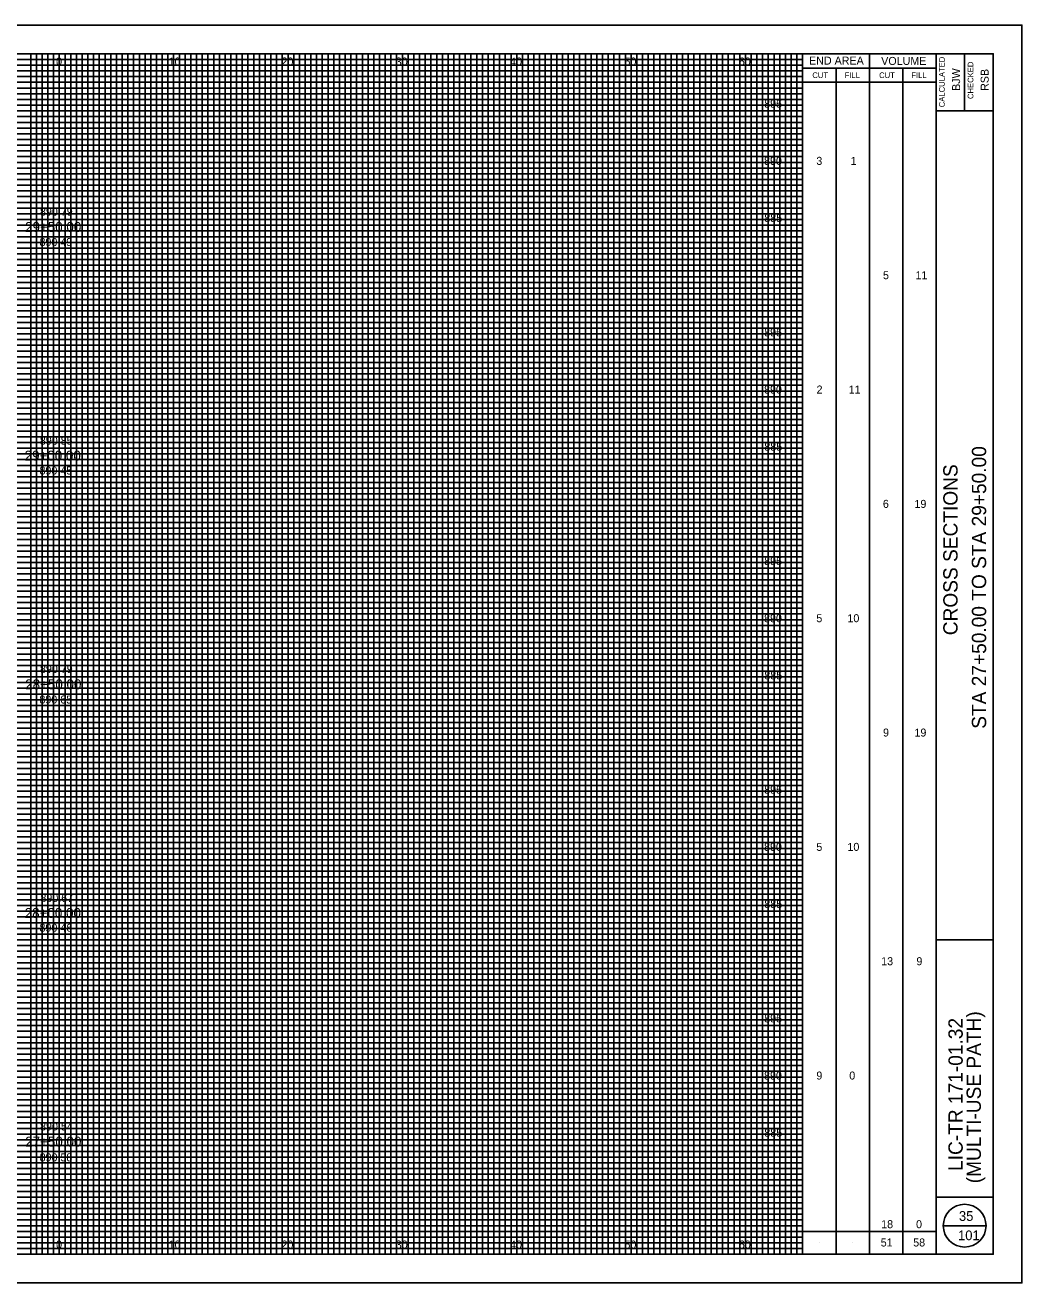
# Model space of a CAD drawing. Extents: x -10 to 160, y -2 to 2522.
# Drawn here: x 72.8 to 160, y 802.5 to 912.5 of the extents above; entities that cross this region are included whole.
import ezdxf

# ---------------------------------------------------------------- set-up
doc = ezdxf.new("R2010")
doc.units = 0
for name, color, linetype in [('GK_Cells', 7, 'Continuous'), ('GK_Patterns', 7, 'Continuous'), ('TX_P_10', 7, 'Continuous'), ('TX_X_10', 7, 'Continuous'), ('XS_P_Finished_Grade_Seeded', 7, 'Continuous'), ('XS_P_Pavt_Surface', 7, 'Continuous'), ('XS_P_Subgrade', 7, 'Continuous'), ('XS_X_Ground_Line', 7, 'Continuous')]:
    doc.layers.add(name, color=color, linetype=linetype)

msp = doc.modelspace()

# ---------------------------------------------------------------- linework, layer by layer
at = {"layer": 'GK_Cells'}
msp.add_lwpolyline([(-10, 802.5), (160, 802.5), (160, 912.5), (-10, 912.5)], close=True, dxfattribs=at)
at = {"layer": 'TX_P_10'}
for p, q in [((140.83, 805), (140.83, 910)), ((146.67, 805), (146.67, 910)), ((140.83, 908.75), (152.5, 908.75)), ((143.75, 805), (143.75, 908.75)), ((149.58, 805), (149.58, 908.75)), ((140.83, 907.5), (152.5, 907.5)), ((153.12, 807.5), (156.88, 807.5)), ((140.83, 807), (152.5, 807)), ((142.29, 806), (142.29, 806)), ((145.21, 806), (145.21, 806)), ((148.12, 806), (148.12, 806)), ((151.04, 806), (151.04, 806))]:
    msp.add_line(p, q, dxfattribs=at)
msp.add_circle((155, 807.5), 1.87, dxfattribs=at)
at = {"layer": 'TX_X_10'}
for p, q in [((75.83, 805), (75.83, 910)), ((80.83, 805), (80.83, 910)), ((85.83, 805), (85.83, 910)), ((90.83, 805), (90.83, 910)), ((95.83, 805), (95.83, 910)), ((100.83, 805), (100.83, 910)), ((105.83, 805), (105.83, 910)), ((110.83, 805), (110.83, 910)), ((115.83, 805), (115.83, 910)), ((120.83, 805), (120.83, 910)), ((125.83, 805), (125.83, 910)), ((130.83, 805), (130.83, 910)), ((135.83, 805), (135.83, 910)), ((5.83, 905), (140.83, 905)), ((5.83, 900), (140.83, 900)), ((5.83, 895), (140.83, 895)), ((5.83, 890), (140.83, 890)), ((5.83, 885), (140.83, 885)), ((5.83, 880), (140.83, 880)), ((5.83, 875), (140.83, 875)), ((5.83, 870), (140.83, 870)), ((5.83, 865), (140.83, 865)), ((5.83, 860), (140.83, 860)), ((5.83, 855), (140.83, 855)), ((5.83, 850), (140.83, 850)), ((5.83, 845), (140.83, 845)), ((5.83, 840), (140.83, 840)), ((5.83, 835), (140.83, 835)), ((5.83, 830), (140.83, 830)), ((5.83, 825), (140.83, 825)), ((5.83, 820), (140.83, 820)), ((5.83, 815), (140.83, 815)), ((5.83, 810), (140.83, 810))]:
    msp.add_line(p, q, dxfattribs=at)
at = {"layer": 'XS_P_Pavt_Surface'}
for p, q in [((152.5, 805), (152.5, 910)), ((155, 910), (155, 905)), ((152.5, 905), (157.5, 905)), ((152.5, 832.5), (157.5, 832.5)), ((152.5, 810), (157.5, 810))]:
    msp.add_line(p, q, dxfattribs=at)
msp.add_lwpolyline([(0, 910), (157.5, 910), (157.5, 805), (0, 805)], close=True, dxfattribs=at)
at = {"layer": 'XS_X_Ground_Line'}
for p, q in [((73.33, 805), (73.33, 910)), ((73.83, 805), (73.83, 910)), ((74.33, 805), (74.33, 910)), ((74.83, 805), (74.83, 910)), ((75.33, 805), (75.33, 910)), ((76.33, 805), (76.33, 910)), ((76.83, 805), (76.83, 910)), ((77.33, 805), (77.33, 910)), ((77.83, 805), (77.83, 910)), ((78.33, 805), (78.33, 910)), ((78.83, 805), (78.83, 910)), ((79.33, 805), (79.33, 910)), ((79.83, 805), (79.83, 910)), ((80.33, 805), (80.33, 910)), ((81.33, 805), (81.33, 910)), ((81.83, 805), (81.83, 910)), ((82.33, 805), (82.33, 910)), ((82.83, 805), (82.83, 910)), ((83.33, 805), (83.33, 910)), ((83.83, 805), (83.83, 910)), ((84.33, 805), (84.33, 910)), ((84.83, 805), (84.83, 910)), ((85.33, 805), (85.33, 910)), ((86.33, 805), (86.33, 910)), ((86.83, 805), (86.83, 910)), ((87.33, 805), (87.33, 910)), ((87.83, 805), (87.83, 910)), ((88.33, 805), (88.33, 910)), ((88.83, 805), (88.83, 910)), ((89.33, 805), (89.33, 910)), ((89.83, 805), (89.83, 910)), ((90.33, 805), (90.33, 910)), ((91.33, 805), (91.33, 910)), ((91.83, 805), (91.83, 910)), ((92.33, 805), (92.33, 910)), ((92.83, 805), (92.83, 910)), ((93.33, 805), (93.33, 910)), ((93.83, 805), (93.83, 910)), ((94.33, 805), (94.33, 910)), ((94.83, 805), (94.83, 910)), ((95.33, 805), (95.33, 910)), ((96.33, 805), (96.33, 910)), ((96.83, 805), (96.83, 910)), ((97.33, 805), (97.33, 910)), ((97.83, 805), (97.83, 910)), ((98.33, 805), (98.33, 910)), ((98.83, 805), (98.83, 910)), ((99.33, 805), (99.33, 910)), ((99.83, 805), (99.83, 910)), ((100.33, 805), (100.33, 910)), ((101.33, 805), (101.33, 910)), ((101.83, 805), (101.83, 910)), ((102.33, 805), (102.33, 910)), ((102.83, 805), (102.83, 910)), ((103.33, 805), (103.33, 910)), ((103.83, 805), (103.83, 910)), ((104.33, 805), (104.33, 910)), ((104.83, 805), (104.83, 910)), ((105.33, 805), (105.33, 910)), ((106.33, 805), (106.33, 910)), ((106.83, 805), (106.83, 910)), ((107.33, 805), (107.33, 910)), ((107.83, 805), (107.83, 910)), ((108.33, 805), (108.33, 910)), ((108.83, 805), (108.83, 910)), ((109.33, 805), (109.33, 910)), ((109.83, 805), (109.83, 910)), ((110.33, 805), (110.33, 910)), ((111.33, 805), (111.33, 910)), ((111.83, 805), (111.83, 910)), ((112.33, 805), (112.33, 910)), ((112.83, 805), (112.83, 910)), ((113.33, 805), (113.33, 910)), ((113.83, 805), (113.83, 910)), ((114.33, 805), (114.33, 910)), ((114.83, 805), (114.83, 910)), ((115.33, 805), (115.33, 910)), ((116.33, 805), (116.33, 910)), ((116.83, 805), (116.83, 910)), ((117.33, 805), (117.33, 910)), ((117.83, 805), (117.83, 910)), ((118.33, 805), (118.33, 910)), ((118.83, 805), (118.83, 910)), ((119.33, 805), (119.33, 910)), ((119.83, 805), (119.83, 910)), ((120.33, 805), (120.33, 910)), ((121.33, 805), (121.33, 910)), ((121.83, 805), (121.83, 910)), ((122.33, 805), (122.33, 910)), ((122.83, 805), (122.83, 910)), ((123.33, 805), (123.33, 910)), ((123.83, 805), (123.83, 910)), ((124.33, 805), (124.33, 910)), ((124.83, 805), (124.83, 910)), ((125.33, 805), (125.33, 910)), ((126.33, 805), (126.33, 910)), ((126.83, 805), (126.83, 910)), ((127.33, 805), (127.33, 910)), ((127.83, 805), (127.83, 910)), ((128.33, 805), (128.33, 910)), ((128.83, 805), (128.83, 910)), ((129.33, 805), (129.33, 910)), ((129.83, 805), (129.83, 910)), ((130.33, 805), (130.33, 910)), ((131.33, 805), (131.33, 910)), ((131.83, 805), (131.83, 910)), ((132.33, 805), (132.33, 910)), ((132.83, 805), (132.83, 910)), ((133.33, 805), (133.33, 910)), ((133.83, 805), (133.83, 910)), ((134.33, 805), (134.33, 910)), ((134.83, 805), (134.83, 910)), ((135.33, 805), (135.33, 910)), ((136.33, 805), (136.33, 910)), ((136.83, 805), (136.83, 910)), ((137.33, 805), (137.33, 910)), ((137.83, 805), (137.83, 910)), ((138.33, 805), (138.33, 910)), ((138.83, 805), (138.83, 910)), ((139.33, 805), (139.33, 910)), ((139.83, 805), (139.83, 910)), ((140.33, 805), (140.33, 910)), ((5.83, 909.5), (140.83, 909.5)), ((5.83, 909), (140.83, 909)), ((5.83, 908.5), (140.83, 908.5)), ((5.83, 908), (140.83, 908)), ((5.83, 907.5), (140.83, 907.5)), ((5.83, 907), (140.83, 907)), ((5.83, 906.5), (140.83, 906.5)), ((5.83, 906), (140.83, 906)), ((5.83, 905.5), (140.83, 905.5)), ((5.83, 904.5), (140.83, 904.5)), ((5.83, 904), (140.83, 904)), ((5.83, 903.5), (140.83, 903.5)), ((5.83, 903), (140.83, 903)), ((5.83, 902.5), (140.83, 902.5)), ((5.83, 902), (140.83, 902)), ((5.83, 901.5), (140.83, 901.5)), ((5.83, 901), (140.83, 901)), ((5.83, 900.5), (140.83, 900.5)), ((5.83, 899.5), (140.83, 899.5)), ((5.83, 899), (140.83, 899)), ((5.83, 898.5), (140.83, 898.5)), ((5.83, 898), (140.83, 898)), ((5.83, 897.5), (140.83, 897.5)), ((5.83, 897), (140.83, 897)), ((5.83, 896.5), (140.83, 896.5)), ((5.83, 896), (140.83, 896)), ((5.83, 895.5), (140.83, 895.5)), ((5.83, 894.5), (140.83, 894.5)), ((5.83, 894), (140.83, 894)), ((5.83, 893.5), (140.83, 893.5)), ((5.83, 893), (140.83, 893)), ((5.83, 892.5), (140.83, 892.5)), ((5.83, 892), (140.83, 892)), ((5.83, 891.5), (140.83, 891.5)), ((5.83, 891), (140.83, 891)), ((5.83, 890.5), (140.83, 890.5)), ((5.83, 889.5), (140.83, 889.5)), ((5.83, 889), (140.83, 889)), ((5.83, 888.5), (140.83, 888.5)), ((5.83, 888), (140.83, 888)), ((5.83, 887.5), (140.83, 887.5)), ((5.83, 887), (140.83, 887)), ((5.83, 886.5), (140.83, 886.5)), ((5.83, 886), (140.83, 886)), ((5.83, 885.5), (140.83, 885.5)), ((5.83, 884.5), (140.83, 884.5)), ((5.83, 884), (140.83, 884)), ((5.83, 883.5), (140.83, 883.5)), ((5.83, 883), (140.83, 883)), ((5.83, 882.5), (140.83, 882.5)), ((5.83, 882), (140.83, 882)), ((5.83, 881.5), (140.83, 881.5)), ((5.83, 881), (140.83, 881)), ((5.83, 880.5), (140.83, 880.5)), ((5.83, 879.5), (140.83, 879.5)), ((5.83, 879), (140.83, 879)), ((5.83, 878.5), (140.83, 878.5)), ((5.83, 878), (140.83, 878)), ((5.83, 877.5), (140.83, 877.5)), ((5.83, 877), (140.83, 877)), ((5.83, 876.5), (140.83, 876.5)), ((5.83, 876), (140.83, 876)), ((5.83, 875.5), (140.83, 875.5)), ((5.83, 874.5), (140.83, 874.5)), ((5.83, 874), (140.83, 874)), ((5.83, 873.5), (140.83, 873.5)), ((5.83, 873), (140.83, 873)), ((5.83, 872.5), (140.83, 872.5)), ((5.83, 872), (140.83, 872)), ((5.83, 871.5), (140.83, 871.5)), ((5.83, 871), (140.83, 871)), ((5.83, 870.5), (140.83, 870.5)), ((5.83, 869.5), (140.83, 869.5)), ((5.83, 869), (140.83, 869)), ((5.83, 868.5), (140.83, 868.5)), ((5.83, 868), (140.83, 868)), ((5.83, 867.5), (140.83, 867.5)), ((5.83, 867), (140.83, 867)), ((5.83, 866.5), (140.83, 866.5)), ((5.83, 866), (140.83, 866)), ((5.83, 865.5), (140.83, 865.5)), ((5.83, 864.5), (140.83, 864.5)), ((5.83, 864), (140.83, 864)), ((5.83, 863.5), (140.83, 863.5)), ((5.83, 863), (140.83, 863)), ((5.83, 862.5), (140.83, 862.5)), ((5.83, 862), (140.83, 862)), ((5.83, 861.5), (140.83, 861.5)), ((5.83, 861), (140.83, 861)), ((5.83, 860.5), (140.83, 860.5)), ((5.83, 859.5), (140.83, 859.5)), ((5.83, 859), (140.83, 859)), ((5.83, 858.5), (140.83, 858.5)), ((5.83, 858), (140.83, 858)), ((5.83, 857.5), (140.83, 857.5)), ((5.83, 857), (140.83, 857)), ((5.83, 856.5), (140.83, 856.5)), ((5.83, 856), (140.83, 856)), ((5.83, 855.5), (140.83, 855.5)), ((5.83, 854.5), (140.83, 854.5)), ((5.83, 854), (140.83, 854)), ((5.83, 853.5), (140.83, 853.5)), ((5.83, 853), (140.83, 853)), ((5.83, 852.5), (140.83, 852.5)), ((5.83, 852), (140.83, 852)), ((5.83, 851.5), (140.83, 851.5)), ((5.83, 851), (140.83, 851)), ((5.83, 850.5), (140.83, 850.5)), ((5.83, 849.5), (140.83, 849.5)), ((5.83, 849), (140.83, 849)), ((5.83, 848.5), (140.83, 848.5)), ((5.83, 848), (140.83, 848)), ((5.83, 847.5), (140.83, 847.5)), ((5.83, 847), (140.83, 847)), ((5.83, 846.5), (140.83, 846.5)), ((5.83, 846), (140.83, 846)), ((5.83, 845.5), (140.83, 845.5)), ((5.83, 844.5), (140.83, 844.5)), ((5.83, 844), (140.83, 844)), ((5.83, 843.5), (140.83, 843.5)), ((5.83, 843), (140.83, 843)), ((5.83, 842.5), (140.83, 842.5)), ((5.83, 842), (140.83, 842)), ((5.83, 841.5), (140.83, 841.5)), ((5.83, 841), (140.83, 841)), ((5.83, 840.5), (140.83, 840.5)), ((5.83, 839.5), (140.83, 839.5)), ((5.83, 839), (140.83, 839)), ((5.83, 838.5), (140.83, 838.5)), ((5.83, 838), (140.83, 838)), ((5.83, 837.5), (140.83, 837.5)), ((5.83, 837), (140.83, 837)), ((5.83, 836.5), (140.83, 836.5)), ((5.83, 836), (140.83, 836)), ((5.83, 835.5), (140.83, 835.5)), ((5.83, 834.5), (140.83, 834.5)), ((5.83, 834), (140.83, 834)), ((5.83, 833.5), (140.83, 833.5)), ((5.83, 833), (140.83, 833)), ((5.83, 832.5), (140.83, 832.5)), ((5.83, 832), (140.83, 832)), ((5.83, 831.5), (140.83, 831.5)), ((5.83, 831), (140.83, 831)), ((5.83, 830.5), (140.83, 830.5)), ((5.83, 829.5), (140.83, 829.5)), ((5.83, 829), (140.83, 829)), ((5.83, 828.5), (140.83, 828.5)), ((5.83, 828), (140.83, 828)), ((5.83, 827.5), (140.83, 827.5)), ((5.83, 827), (140.83, 827)), ((5.83, 826.5), (140.83, 826.5)), ((5.83, 826), (140.83, 826)), ((5.83, 825.5), (140.83, 825.5)), ((5.83, 824.5), (140.83, 824.5)), ((5.83, 824), (140.83, 824)), ((5.83, 823.5), (140.83, 823.5)), ((5.83, 823), (140.83, 823)), ((5.83, 822.5), (140.83, 822.5)), ((5.83, 822), (140.83, 822)), ((5.83, 821.5), (140.83, 821.5)), ((5.83, 821), (140.83, 821)), ((5.83, 820.5), (140.83, 820.5)), ((5.83, 819.5), (140.83, 819.5)), ((5.83, 819), (140.83, 819)), ((5.83, 818.5), (140.83, 818.5)), ((5.83, 818), (140.83, 818)), ((5.83, 817.5), (140.83, 817.5)), ((5.83, 817), (140.83, 817)), ((5.83, 816.5), (140.83, 816.5)), ((5.83, 816), (140.83, 816)), ((5.83, 815.5), (140.83, 815.5)), ((5.83, 814.5), (140.83, 814.5)), ((5.83, 814), (140.83, 814)), ((5.83, 813.5), (140.83, 813.5)), ((5.83, 813), (140.83, 813)), ((5.83, 812.5), (140.83, 812.5)), ((5.83, 812), (140.83, 812)), ((5.83, 811.5), (140.83, 811.5)), ((5.83, 811), (140.83, 811)), ((5.83, 810.5), (140.83, 810.5)), ((5.83, 809.5), (140.83, 809.5)), ((5.83, 809), (140.83, 809)), ((5.83, 808.5), (140.83, 808.5)), ((5.83, 808), (140.83, 808)), ((5.83, 807.5), (140.83, 807.5)), ((5.83, 807), (140.83, 807)), ((5.83, 806.5), (140.83, 806.5)), ((5.83, 806), (140.83, 806)), ((5.83, 805.5), (140.83, 805.5))]:
    msp.add_line(p, q, dxfattribs=at)

# ---------------------------------------------------------------- texts
at = {"layer": 'GK_Patterns'}
for s, height, p in [('0', 0.7, (75.55, 908.97)), ('0', 0.7, (75.55, 908.97)), ('10', 0.7, (85.39, 908.97)), ('20', 0.7, (95.26, 908.97)), ('30', 0.7, (105.25, 908.97)), ('40', 0.7, (115.25, 908.97)), ('50', 0.7, (125.25, 908.97)), ('60', 0.7, (135.25, 908.97)), ('895', 0.7, (137.47, 905.28)), ('890', 0.7, (137.46, 900.28)), ('3', 0.7, (142.03, 900.28)), ('1', 0.7, (145.03, 900.28)), ('885', 0.7, (137.48, 895.28)), ('29+50.00', 0.875, (72.84, 894.41)), ('5', 0.7, (147.86, 890.28)), ('11', 0.7, (150.7, 890.28)), ('895', 0.7, (137.47, 885.28)), ('890', 0.7, (137.46, 880.28)), ('2', 0.7, (142.05, 880.28)), ('11', 0.7, (144.86, 880.28)), ('885', 0.7, (137.48, 875.28)), ('29+00.00', 0.875, (72.8, 874.41)), ('6', 0.7, (147.85, 870.28)), ('19', 0.7, (150.61, 870.28)), ('895', 0.7, (137.47, 865.28)), ('890', 0.7, (137.46, 860.28)), ('5', 0.7, (142.03, 860.28)), ('10', 0.7, (144.75, 860.28)), ('885', 0.7, (137.48, 855.28)), ('28+50.00', 0.875, (72.85, 854.41)), ('9', 0.7, (147.86, 850.28)), ('19', 0.7, (150.61, 850.28)), ('895', 0.7, (137.47, 845.28)), ('890', 0.7, (137.46, 840.28)), ('5', 0.7, (142.03, 840.28)), ('10', 0.7, (144.75, 840.28)), ('28+00.00', 0.875, (72.81, 834.41)), ('885', 0.7, (137.48, 835.28)), ('13', 0.7, (147.7, 830.28)), ('9', 0.7, (150.78, 830.28)), ('895', 0.7, (137.47, 825.28)), ('890', 0.7, (137.46, 820.28)), ('9', 0.7, (142.03, 820.28)), ('0', 0.7, (144.91, 820.28)), ('27+50.00', 0.875, (72.85, 814.41)), ('885', 0.7, (137.48, 815.28)), ('18', 0.7, (147.7, 807.28)), ('0', 0.7, (150.75, 807.28)), ('51', 0.7, (147.66, 805.68)), ('58', 0.7, (150.5, 805.68)), ('0', 0.7, (75.55, 805.5)), ('0', 0.7, (75.55, 805.5)), ('10', 0.7, (85.39, 805.5)), ('20', 0.7, (95.26, 805.5)), ('30', 0.7, (105.25, 805.5)), ('40', 0.7, (115.25, 805.5)), ('50', 0.7, (125.25, 805.5)), ('60', 0.7, (135.25, 805.5))]:
    msp.add_text(s, height=height, dxfattribs=at).set_placement(p)
at = {"layer": 'TX_P_10'}
for s, height, p in [('END AREA', 0.7, (141.39, 909.05)), ('VOLUME', 0.7, (147.7, 909.02)), ('CUT', 0.5, (141.68, 907.87)), ('FILL', 0.5, (144.5, 907.87)), ('CUT', 0.5, (147.52, 907.87)), ('FILL', 0.5, (150.34, 907.87)), ('35', 0.85, (154.5, 807.92)), ('101', 0.85, (154.42, 806.23))]:
    msp.add_text(s, height=height, dxfattribs=at).set_placement(p)
for s, height, p in [('CALCULATED', 0.5, (153.26, 905.32)), ('BJW', 0.7, (154.6, 906.75)), ('CHECKED', 0.5, (155.76, 906.04)), ('RSB', 0.7, (157.1, 906.75)), ('STA 27+50.00 TO STA 29+50.00', 1.25, (156.88, 850.96)), ('CROSS SECTIONS', 1.25, (154.38, 859.14)), ('(MULTI-USE PATH)', 1.25, (156.42, 811.21)), ('LIC-TR 171-01.32', 1.25, (154.83, 812.29))]:
    msp.add_text(s, height=height, rotation=90, dxfattribs=at).set_placement(p)
at = {"layer": 'XS_P_Finished_Grade_Seeded'}
for s, p in [('890.49', (74.1, 893.18)), ('890.45', (74.1, 873.2)), ('890.65', (74.09, 853.17)), ('890.46', (74.1, 833.21)), ('890.58', (74.11, 813.13))]:
    msp.add_text(s, height=0.7, dxfattribs=at).set_placement(p)
at = {"layer": 'XS_P_Subgrade'}
for s, p in [('890.79', (74.14, 895.84)), ('890.85', (74.13, 875.81)), ('890.79', (74.14, 855.84)), ('890.67', (74.18, 835.81)), ('890.54', (74.15, 815.83))]:
    msp.add_text(s, height=0.7, dxfattribs=at).set_placement(p)

doc.saveas('drawing.dxf')
